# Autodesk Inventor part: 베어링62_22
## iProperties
Created: 2009-02
Part Number: 베어링62_22
Material: 강, 연강
Description: 깊은 그루브 볼 베어링
Document SubType Name: Modeling
Standard: KS B 2023
Designer: KYOUNG IL JANG
Standards Organization: KS
Language: ko-KR
Size Designation: 62/22 - 22 x 50 x 14
Categories: <MemberInstance><Categories><Category DisplayName="샤프트 부품" InternalName="7f7aeb1f-a693-4053-b835-cee3144e0d98" Mnemonic="SHFT"><Category DisplayName="베어링" Inter
Density: 1 g/cm^3
IsCustomPart: 0
Author: KYOUNG IL JANG
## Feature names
1. IDS_ARRAYBALL[SIMPL:T] [Circular Pattern]
